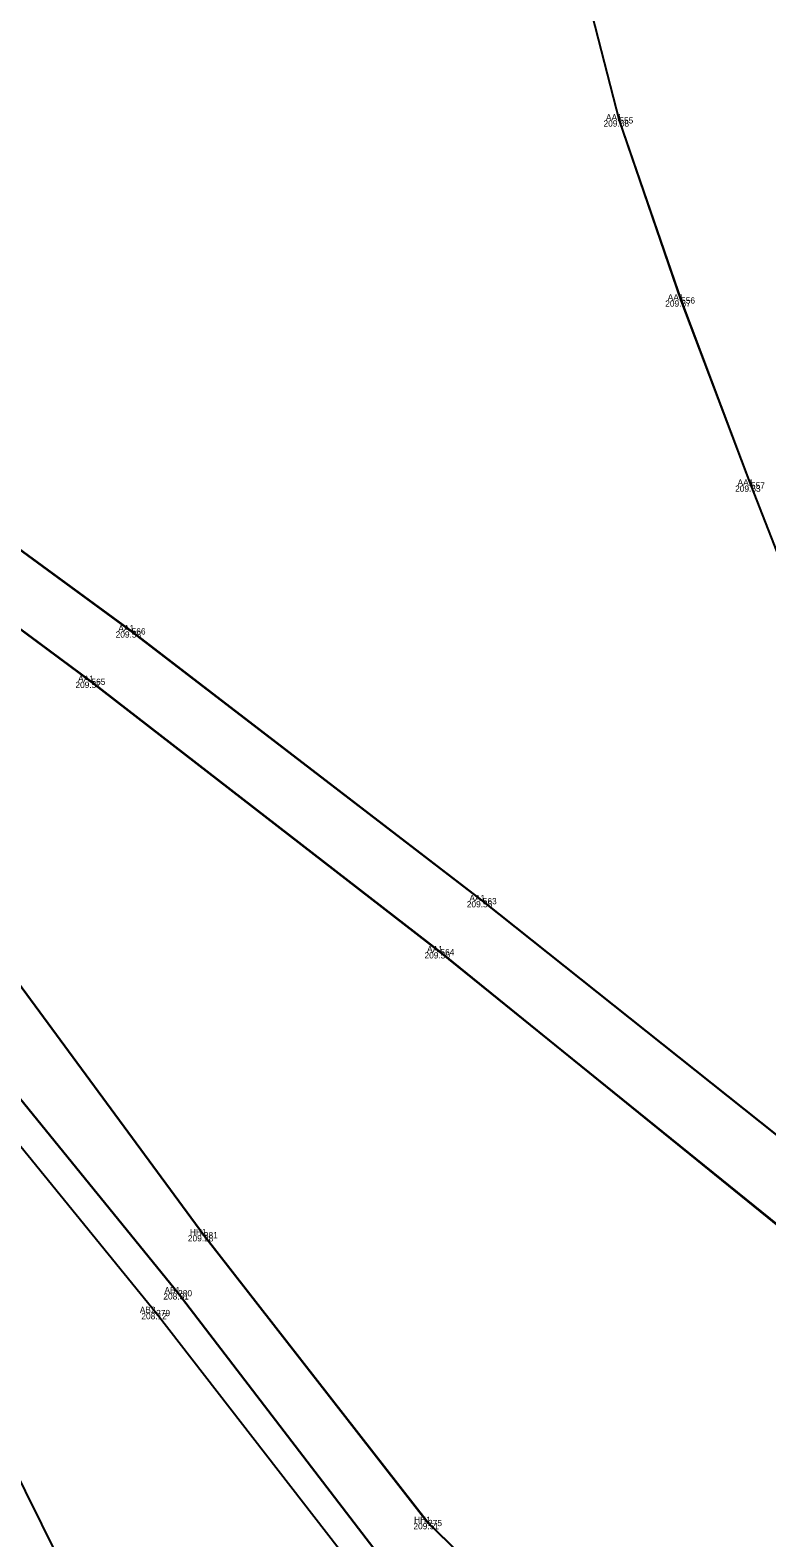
# Model space of a CAD drawing. Extents: x -263091 to -262565, y -1238731 to -1237092.
# Drawn here: x -262930.86 to -262907.26, y -1238442.76 to -1238394.45 of the extents above; entities that cross this region are included whole.
import ezdxf

# ---------------------------------------------------------------- set-up
doc = ezdxf.new("R2010")
doc.units = 0
for name, color, linetype in [('01_Hrana_betónu', 7, 'Continuous'), ('03_Asfalt', 7, 'Continuous'), ('05_Hrana_terénu', 7, 'Continuous'), ('10', 7, 'Continuous'), ('Groma (21)', 7, 'Continuous'), ('Groma (22)', 7, 'Continuous'), ('Groma (23)', 7, 'Continuous'), ('Groma (24)', 7, 'Continuous'), ('U001_Betónové_panely_oblast', 7, 'Continuous'), ('U001_Zeleň_mimo', 7, 'Continuous'), ('U001_Zeleň_zatrávňovač', 7, 'Continuous'), ('U002_Asfalt', 7, 'Continuous'), ('U002_Zeleň_mimo', 7, 'Continuous')]:
    doc.layers.add(name, color=color, linetype=linetype)

msp = doc.modelspace()

# ---------------------------------------------------------------- linework, layer by layer
at = {"layer": '01_Hrana_betónu'}
for points in [[(-262919.416, -1238445.121), (-262926.823, -1238435.554), (-262934.526, -1238426.105), (-262939.342, -1238418.342), (-262940.205, -1238415.315), (-262939.384, -1238414.863)], [(-262939.384, -1238414.863), (-262938.574, -1238417.919), (-262933.765, -1238425.512), (-262926.119, -1238434.921), (-262918.733, -1238444.559)], [(-262821.555, -1238690.42), (-262822.731, -1238690.203), (-262823.426, -1238689.509), (-262824.318, -1238680.43), (-262831.163, -1238660.976), (-262837.946, -1238643.111), (-262846.365, -1238620.94), (-262852.333, -1238605.156), (-262858.618, -1238590.245), (-262867.784, -1238570.905), (-262871.416, -1238563.68), (-262881.223, -1238544.283), (-262888.392, -1238529.442), (-262892.626, -1238519.239), (-262901.725, -1238500.385), (-262911.6, -1238480.51), (-262921.479, -1238460.51), (-262932.607, -1238438.043), (-262939.752, -1238424.147), (-262940.771, -1238420.267), (-262940.559, -1238417.612), (-262940.205, -1238415.315)]]:
    msp.add_lwpolyline(points, dxfattribs=at)
at = {"layer": '03_Asfalt'}
for points in [[(-262913.444, -1238391.676), (-262911.985, -1238397.337), (-262910.006, -1238403.107), (-262907.769, -1238409.039), (-262901.709, -1238424.56), (-262896.942, -1238436.871), (-262897.547, -1238437.016), (-262898.706, -1238436.381), (-262904.848, -1238431.522), (-262916.36, -1238422.355), (-262927.608, -1238413.712), (-262940.472, -1238404.296), (-262944.235, -1238401.54), (-262944.94, -1238400.579), (-262945.063, -1238399.495), (-262942.635, -1238399.58), (-262939.962, -1238399.183), (-262936.84, -1238398.276), (-262934.121, -1238396.673), (-262931.78, -1238394.73), (-262927.567, -1238384.599)], [(-262804.465, -1238690.033), (-262818.631, -1238655.736), (-262826.695, -1238636.389), (-262836.855, -1238611.872), (-262842.406, -1238598.306), (-262850.452, -1238578.707), (-262858.82, -1238561.234), (-262870.509, -1238539), (-262873.344, -1238533.53), (-262876.375, -1238529.239), (-262880.031, -1238521.826), (-262869.115, -1238517.45), (-262870.175, -1238508.052), (-262871.319, -1238501.744), (-262886.895, -1238462.375), (-262895.067, -1238441.663), (-262905.824, -1238433.621), (-262917.716, -1238423.993), (-262928.896, -1238415.327), (-262941.774, -1238405.784), (-262954.673, -1238396.412), (-262962.054, -1238391.026)]]:
    msp.add_lwpolyline(points, dxfattribs=at)
at = {"layer": '05_Hrana_terénu'}
msp.add_lwpolyline([(-262927.783, -1238467.254), (-262930.465, -1238462.525), (-262936.779, -1238449.928), (-262947.402, -1238428.273), (-262948.67, -1238426), (-262950.05, -1238420.42), (-262949.48, -1238414.85), (-262946.99, -1238412.24), (-262943.77, -1238411.76), (-262937.85, -1238412.69), (-262935.589, -1238416.796), (-262931.931, -1238424.05), (-262925.295, -1238433.06), (-262918.113, -1238442.283), (-262917.125, -1238443.234)], dxfattribs=at)
at = {"layer": '10'}
msp.add_lwpolyline([(-262982.434, -1238375.977), (-262968.907, -1238386.238), (-262962.054, -1238391.026), (-262954.673, -1238396.412), (-262941.774, -1238405.784), (-262928.896, -1238415.327), (-262917.716, -1238423.993), (-262905.824, -1238433.621), (-262895.067, -1238441.663), (-262870.407, -1238460.6)], dxfattribs=at)
at = {"layer": 'Groma (21)'}
for centre in [(-262911.985, -1238397.337), (-262910.006, -1238403.107), (-262907.769, -1238409.039), (-262927.608, -1238413.712), (-262928.896, -1238415.327), (-262916.36, -1238422.355), (-262917.716, -1238423.993), (-262925.295, -1238433.06), (-262926.119, -1238434.921), (-262926.823, -1238435.554), (-262918.113, -1238442.283)]:
    msp.add_circle(centre, 0.01, dxfattribs=at)
at = {"layer": 'U001_Betónové_panely_oblast'}
msp.add_lwpolyline([(-262907.49, -1238505.36), (-262916.81, -1238486.58), (-262927.85, -1238464.09), (-262935.21, -1238449.19), (-262946.95, -1238425.6), (-262948.22, -1238419.38), (-262947.72, -1238416.17), (-262946.81, -1238414.66), (-262945.17, -1238414.02), (-262945.09, -1238415.05), (-262943.96, -1238415.15), (-262941.14, -1238415.31), (-262940.21, -1238415.32), (-262939.38, -1238414.86), (-262938.57, -1238417.92), (-262933.77, -1238425.51), (-262926.12, -1238434.92), (-262918.73, -1238444.56), (-262919.42, -1238445.12), (-262914.36, -1238451.38), (-262913.6, -1238450.89), (-262908.88, -1238459.13), (-262904.31, -1238470.05)], dxfattribs=at)
msp.add_lwpolyline([(-262907.49, -1238505.36), (-262916.81, -1238486.58), (-262927.85, -1238464.09), (-262935.21, -1238449.19), (-262946.95, -1238425.6), (-262948.22, -1238419.38), (-262947.72, -1238416.17), (-262946.81, -1238414.66), (-262945.17, -1238414.02), (-262945.09, -1238415.05), (-262943.96, -1238415.15), (-262941.14, -1238415.31), (-262940.21, -1238415.32), (-262939.38, -1238414.86), (-262938.57, -1238417.92), (-262933.77, -1238425.51), (-262926.12, -1238434.92), (-262918.73, -1238444.56), (-262919.42, -1238445.12), (-262914.36, -1238451.38), (-262913.6, -1238450.89), (-262908.88, -1238459.13), (-262904.31, -1238470.05)], dxfattribs=at)
at = {"layer": 'U001_Zeleň_mimo'}
for points in [[(-262962.05, -1238391.03), (-262954.67, -1238396.41), (-262941.77, -1238405.78), (-262928.9, -1238415.33), (-262917.72, -1238423.99), (-262905.82, -1238433.62), (-262895.07, -1238441.66), (-262886.9, -1238462.38), (-262871.32, -1238501.74), (-262870.18, -1238508.05), (-262869.12, -1238517.45), (-262880.03, -1238521.83), (-262876.38, -1238529.24), (-262873.34, -1238533.53), (-262870.51, -1238539), (-262858.82, -1238561.23), (-262850.45, -1238578.71), (-262842.41, -1238598.31), (-262836.86, -1238611.87), (-262826.7, -1238636.39), (-262818.63, -1238655.74), (-262804.47, -1238690.03)], [(-262902.96, -1238468.81), (-262907.91, -1238457.21), (-262911.31, -1238451.07), (-262911.84, -1238449.79), (-262917.13, -1238443.23), (-262918.11, -1238442.28), (-262925.3, -1238433.06), (-262931.93, -1238424.05), (-262935.59, -1238416.8), (-262935.96, -1238414.87), (-262937.48, -1238412.22), (-262943.77, -1238411.76), (-262954.62, -1238410.7), (-262953.69, -1238416.69), (-262950.95, -1238424.18), (-262948.2, -1238429.71), (-262938.08, -1238450.42), (-262931.82, -1238462.79), (-262930.86, -1238463.25), (-262933.04, -1238464.36), (-262929.78, -1238468.68), (-262929.26, -1238468.08), (-262919.31, -1238488.27), (-262908.34, -1238509.94)]]:
    msp.add_lwpolyline(points, dxfattribs=at)
at = {"layer": 'U001_Zeleň_zatrávňovač'}
for points in [[(-262936.78, -1238449.93), (-262947.4, -1238428.27), (-262948.67, -1238426), (-262950.05, -1238420.42), (-262949.48, -1238414.85), (-262946.99, -1238412.24), (-262943.77, -1238411.76), (-262937.85, -1238412.69), (-262935.59, -1238416.8), (-262931.93, -1238424.05), (-262925.3, -1238433.06), (-262918.11, -1238442.28), (-262917.13, -1238443.23)], [(-262936.78, -1238449.93), (-262947.4, -1238428.27), (-262948.67, -1238426), (-262950.05, -1238420.42), (-262949.48, -1238414.85), (-262946.99, -1238412.24), (-262943.77, -1238411.76), (-262937.85, -1238412.69), (-262935.59, -1238416.8), (-262931.93, -1238424.05), (-262925.3, -1238433.06), (-262918.11, -1238442.28), (-262917.13, -1238443.23)], [(-262918.73, -1238444.56), (-262926.12, -1238434.92), (-262933.77, -1238425.51), (-262938.57, -1238417.92), (-262939.38, -1238414.86), (-262940.21, -1238415.32), (-262940.22, -1238414.78), (-262945.07, -1238414.56), (-262945.17, -1238414.02), (-262946.81, -1238414.66), (-262947.72, -1238416.17), (-262948.22, -1238419.38), (-262946.95, -1238425.6), (-262935.21, -1238449.19)], [(-262918.73, -1238444.56), (-262926.12, -1238434.92), (-262933.77, -1238425.51), (-262938.57, -1238417.92), (-262939.38, -1238414.86), (-262940.21, -1238415.32), (-262940.22, -1238414.78), (-262945.07, -1238414.56), (-262945.17, -1238414.02), (-262946.81, -1238414.66), (-262947.72, -1238416.17), (-262948.22, -1238419.38), (-262946.95, -1238425.6), (-262935.21, -1238449.19)]]:
    msp.add_lwpolyline(points, dxfattribs=at)
at = {"layer": 'U002_Asfalt'}
for points in [[(-262927.57, -1238384.6), (-262931.78, -1238394.73), (-262934.12, -1238396.67), (-262936.84, -1238398.28), (-262939.96, -1238399.18), (-262942.64, -1238399.58), (-262945.06, -1238399.5), (-262944.94, -1238400.58), (-262944.24, -1238401.54), (-262940.47, -1238404.3), (-262927.61, -1238413.71), (-262916.36, -1238422.36), (-262904.85, -1238431.52), (-262898.71, -1238436.38), (-262897.55, -1238437.02), (-262896.94, -1238436.87), (-262895.07, -1238441.66), (-262905.82, -1238433.62), (-262917.72, -1238423.99), (-262928.9, -1238415.33), (-262941.77, -1238405.78), (-262954.67, -1238396.41), (-262962.05, -1238391.03)], [(-262927.57, -1238384.6), (-262931.78, -1238394.73), (-262934.12, -1238396.67), (-262936.84, -1238398.28), (-262939.96, -1238399.18), (-262942.64, -1238399.58), (-262945.06, -1238399.5), (-262944.94, -1238400.58), (-262944.24, -1238401.54), (-262940.47, -1238404.3), (-262927.61, -1238413.71), (-262916.36, -1238422.36), (-262904.85, -1238431.52), (-262898.71, -1238436.38), (-262897.55, -1238437.02), (-262896.94, -1238436.87), (-262895.07, -1238441.66)], [(-262895.07, -1238441.66), (-262905.82, -1238433.62), (-262917.72, -1238423.99), (-262928.9, -1238415.33), (-262941.77, -1238405.78), (-262954.67, -1238396.41), (-262962.05, -1238391.03)]]:
    msp.add_lwpolyline(points, dxfattribs=at)
at = {"layer": 'U002_Zeleň_mimo'}
msp.add_lwpolyline([(-262913.44, -1238391.68), (-262911.99, -1238397.34), (-262910.01, -1238403.11), (-262907.77, -1238409.04), (-262901.71, -1238424.56), (-262896.94, -1238436.87), (-262897.55, -1238437.02), (-262898.71, -1238436.38), (-262904.85, -1238431.52), (-262916.36, -1238422.36), (-262927.61, -1238413.71), (-262940.47, -1238404.3), (-262944.24, -1238401.54), (-262944.94, -1238400.58), (-262945.06, -1238399.5), (-262942.64, -1238399.58), (-262939.96, -1238399.18), (-262936.84, -1238398.28), (-262934.12, -1238396.67), (-262931.78, -1238394.73), (-262927.57, -1238384.6)], dxfattribs=at)

# ---------------------------------------------------------------- texts
at = {"layer": 'Groma (22)'}
for s, p in [('555', (-262911.985, -1238397.437)), ('556', (-262910.006, -1238403.207)), ('557', (-262907.769, -1238409.139)), ('566', (-262927.608, -1238413.812)), ('565', (-262928.896, -1238415.427)), ('563', (-262916.36, -1238422.455)), ('564', (-262917.716, -1238424.093)), ('281', (-262925.295, -1238433.16)), ('280', (-262926.119, -1238435.021)), ('279', (-262926.823, -1238435.654)), ('275', (-262918.113, -1238442.383))]:
    msp.add_text(s, height=0.2, dxfattribs=at).set_placement(p)
at = {"layer": 'Groma (23)'}
for s, p in [('209.68', (-262912.492, -1238397.537)), ('209.67', (-262910.514, -1238403.307)), ('209.63', (-262908.276, -1238409.239)), ('209.58', (-262928.12, -1238413.912)), ('209.57', (-262929.409, -1238415.527)), ('209.55', (-262916.872, -1238422.555)), ('209.50', (-262918.227, -1238424.193)), ('209.28', (-262925.807, -1238433.26)), ('208.51', (-262926.592, -1238435.121)), ('208.12', (-262927.296, -1238435.754)), ('209.51', (-262918.581, -1238442.483))]:
    msp.add_text(s, height=0.2, dxfattribs=at).set_placement(p)
at = {"layer": 'Groma (24)'}
for s, p in [('AA1', (-262912.413, -1238397.337)), ('AA1', (-262910.434, -1238403.107)), ('AA1', (-262908.197, -1238409.039)), ('AA1', (-262928.036, -1238413.712)), ('AA1', (-262929.324, -1238415.327)), ('AA1', (-262916.788, -1238422.355)), ('AA1', (-262918.144, -1238423.993)), ('HH1', (-262925.742, -1238433.06)), ('AB1', (-262926.557, -1238434.921)), ('AB2', (-262927.347, -1238435.554)), ('HH1', (-262918.56, -1238442.283))]:
    msp.add_text(s, height=0.2, dxfattribs=at).set_placement(p)

doc.saveas('drawing.dxf')
